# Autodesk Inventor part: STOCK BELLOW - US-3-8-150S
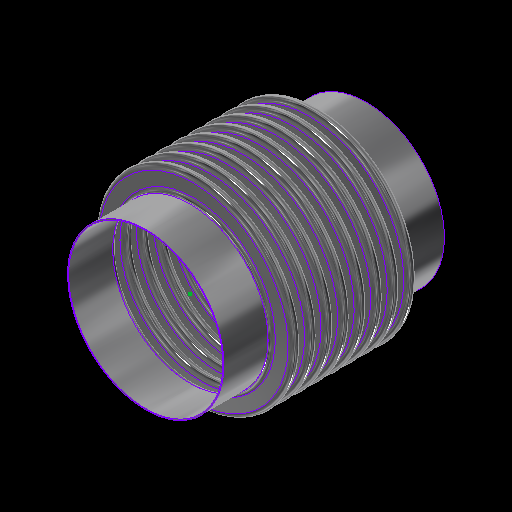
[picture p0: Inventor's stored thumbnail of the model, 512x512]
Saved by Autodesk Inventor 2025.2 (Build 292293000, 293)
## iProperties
Category: 24 GA (0.024 THICK)
RuleStatus: InUse
Created: 2024-01
Part Number: STOCK BELLOW - US-3-8-150S
Project: =STOCK BELLOWS: <Stock Number><SFILL>
Material: ASTM A240-304
Description: =STOCK BELLOWS: <Stock Number>, <SID_> I.D., <SOD_> O.D., <SPLY_> PLY, <Category>, <SNET_CONS> CONS.<PITCH_><STANGENT_> TANGENT<SFILL>
Document SubType Name: Sheet Metal
Designer: GS
Stock Number: U.S-3-8-150S
Surface Area: 1808.55 cm^2
Volume: 54.8112 cm^3
Sheet Metal Rule: Default
Appearance: STAINLESS STEEL
Mass: 441.629 g
Density: 8.05729 g/cm^3
THK: 0.036
ID: 3.500
OD: 4.250
CONS_: 2
PITCH: 0.500
TANGENT: 0.500
BELLOWS_UPSET: 0.000
d79: 1.000
d82: 1.000
d83: 26.000
d84: 24.000
d174: 8
d214: 8
STHK_: 0.024
SID_: 3.500
SOD_: 4.500
SPITCH_: 0.375
STANGENT__: 1.000
SBELLOWS_UPSET_: 0.000
SDIFF_TAN: 1.000
d252: 2
d275: 2
d287: 0.050
d289: 0.500
d290: 0.000
SOD_NECK: 3 9/16
PLY: 1
PSET: 4.178
PBAR: 1.035
COUNTER: 1.500
NET_TUBE: 3.071
CONS: 2
S_CONS: 0
NET_CONS: 2
ID_M: 88.90 mm
OD_M: 107.95 mm
THK_M: 0.91 mm
ID_U: 3.500 in
OD_U: 4.250 in
THK_U: 0.036 in
TANGENT2: 0.500
TAN_TO_TAN: 1.000 in
d80: 2.571
d81: 10
SID: 2.375
SCONS_: 8
SPITCH: 0.250
STANGENT_: 1.000
SBELLOWS_UPSET: 0.000
SNET_CONS: 8
SS_CONS: 0
SCONS: 8
d190: 8
d191: 1
d192: 1
d193: 8
d194: 0
SIZE: 3.00
PRESSURE: 150
d230: 8
STANGENT: 4.000
SPLY_: 1
d233: 8
d234: 0
d263: 2
d265: 1
d268: 2
d269: 0
d286: 2
d288: 1
d291: 2
d292: 0
SREROLL: 0.750
BLETP: 0.000 ul
PRES_Copy: 85
MATTABLE: 20 GA (0.036 THICK)
PART_NUMBER: U.S-3-8-150S
PITCH_: =, <SPITCH_> PITCH,
CFILL: .
SFILL: .
MESH: ,
COMP: 0.66
EXT: 0.33
LAT: 0.16
ANG: 573
ASR: 950
LSR: 2281
ANSR: 30
PRES: 150
COMPM: 6.6
EXTM: 3.3
LATM: 1.60
ASRM: 166.374
PRESM: 10.342
LSRM: 399.472
ANSRM: 5.254
TEMPMIN: 20
TEMPMAX: 800
TEMPMINM: -7
TEMPMAXM: 427
WEIGHTM: 0.442
WEIGHT: 0.974
Author: GS
Keywords: 20 GA (0.036 THICK)
Comments: =STOCK BELLOW - <STOCK NUMBER>
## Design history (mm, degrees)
sketch "Sketch2"
  geometry: L1 (0, -177.245)-(0, 562.856) reference; L2 (45.364, 0)-(44.45, 0); L3 (48.082, -2.718)-(50.343, -2.718); L4 (48.082, -3.632)-(50.343, -3.632); L5 (50.343, -9.982)-(48.082, -9.982); L6 (50.343, -9.068)-(48.082, -9.068); L7 (45.364, -12.7)-(44.45, -12.7); L8 (48.082, 0)-(48.082, -12.7); L9 (50.343, -6.35)-(53.975, -6.35); L10 (44.45, 0)-(44.45, -12.7); L11 (20.376, 102.841)-(20.376, 101.926); L12 (58.262, 457.127)-(58.262, 349.177); L13 (58.262, 444.427)-(58.262, 336.477); L14 (93.133, -58.817)-(93.133, -71.517); L15 (118.746, -66.401)-(118.746, -66.401); L16 (50.343, -9.068)-(50.343, -9.982); L17 (48.082, -9.068)-(48.082, -9.982); L18 (48.082, -9.525)-(50.343, -9.525); L19 (53.975, 0)-(53.975, -12.7); L20 (-50.343, -9.068)-(-50.343, -9.982); L21 (-50.343, -2.718)-(-48.082, -2.718); L22 (-50.343, -3.632)-(-48.082, -3.632); L23 (-48.082, -9.068)-(-50.343, -9.068); L24 (-50.343, -9.525)-(-48.082, -9.525); L25 (-48.082, -9.982)-(-50.343, -9.982); L26 (-48.082, -9.068)-(-48.082, -9.982); L27 (-44.45, 0.653)-(-44.45, -12.047); L28 (-48.082, -6.35)-(-44.45, -6.35); L29 (-50.343, 0.653)-(-50.343, -12.7); L30 (-53.061, 0)-(-53.975, 0); L31 (-53.975, 0)-(-53.975, -12.7); L32 (-53.061, -12.7)-(-53.975, -12.7); A1 r 2.718 centre (48.082, 0) between (45.364, 0) and (48.082, -2.718); A2 r 3.632 centre (48.082, 0) between (44.45, 0) and (48.082, -3.632); A3 r 3.632 centre (50.343, -6.35) between (50.343, -9.982) and (50.343, -2.718); A4 r 2.718 centre (50.343, -6.35) between (50.343, -9.068) and (50.343, -3.632); A5 r 2.718 centre (48.082, -12.7) between (48.082, -9.982) and (45.364, -12.7); A6 r 3.632 centre (48.082, -12.7) between (48.082, -9.068) and (44.45, -12.7); A7 r 3.175 centre (50.343, -6.35) between (50.343, -9.525) and (53.518, -6.35); A8 r 3.175 centre (48.082, -12.7) between (48.082, -9.525) and (44.907, -12.7); A9 r 2.718 centre (-50.343, -12.7) between (-50.343, -9.982) and (-53.061, -12.7); A10 r 2.718 centre (-48.082, -6.35) between (-48.082, -9.068) and (-48.082, -3.632); A11 r 3.175 centre (-48.082, -6.35) between (-48.082, -9.525) and (-44.907, -6.35); A12 r 3.632 centre (-48.082, -6.35) between (-48.082, -9.982) and (-48.082, -2.718); A13 r 3.175 centre (-50.343, -12.7) between (-50.343, -9.525) and (-53.518, -12.7); A14 r 3.632 centre (-50.343, -12.7) between (-50.343, -9.068) and (-53.975, -12.7); A15 r 2.718 centre (-50.343, 0) between (-53.061, 0) and (-50.343, -2.718); A16 r 3.632 centre (-50.343, 0) between (-53.975, 0) and (-50.343, -3.632); 10 further points
  constraints: 62 end point, 38 point on circle, 20 tangent, 16 centre point, 12 parallel, 9 midpoint, 7 vertical, 6 coincident, 6 concentric, 6 point on line, 4 equal radius, 4 perpendicular, 3 horizontal, 1 collinear, 1 horizontal alignment, 10 other
  dimensions: "THK" = 0.9144 distance of L11.start L11.end; "ID" = 88.9 distance of L11.end point (20.376, 13.026); "OD" = 107.95 distance of L12.start L12.end; "PITCH" = 12.7 distance of L12.start L13.start; "TANGENT" = 12.7 distance of L14.start L14.end; "BELLOWS_UPSET" = 0 distance of L15.start L15.end; "d43" = 88.9 diameter of L10 L1 (= ID); "d44" = 107.95 diameter of L9.end L1 (= OD); "d45" = 0.9144 distance between parallel lines of L5 L6 (computed from THK, PLY); "d46" = 3.6322 radius of A3 (computed from PITCH, THK, PLY); "UPSET_PITCH" = 12.7 distance of L2.end L7.end (derived); "SIDEWALL_ANGLE" = 360 deg dimension on L3 L9 (derived); "CON_GAP" = 5.4356 distance of point (48.082, -9.068) point (48.082, -3.632) (derived); "TAN1" = 4.98728 dimension on A8 (derived); "TAN2" = 4.98728 dimension on A7 (derived); "LEG1" = 2.2606 distance of L18.start L18.end (derived); "d278" = 0.9144 distance between parallel lines of L25 L23 (derived); "d279" = 3.6322 radius of A12 (derived); "d280" = 12.7 distance of L30.end L31.end (derived); "d281" = 360 deg dimension on L21 L28 (derived); "d282" = 5.4356 distance of point (-50.343, -9.068) point (-50.343, -3.632) (derived); "d283" = 4.98728 dimension on A13 (derived); "d284" = 4.98728 dimension on A11 (derived); "d285" = 2.2606 distance of L24.start L24.end (derived); "d293" = 88.9 diameter of L27 L1 (derived); "d294" = 107.95 diameter of L31 L1 (derived)
  node "Sketch Rectangular Pattern1" dims "d31" = 25.4, "ID" = 88.9
  node "Sketch Rectangular Pattern2" dims "d39" = 25.4, "PITCH" = 12.7
revolve "CONS" stored, may be unused: angle "d48" = 90 deg
node "BELLOW MIDPLANE"
pattern_linear "Rectangular Pattern2" dims "d52" = 12.7 (= UPSET_PITCH)
sketch "Sketch5"
  geometry: C1 r 45.364 at (0, 0) reference; C2 r 44.45 at (0, 0) reference
extrude "TANGENT" new body sketch "Sketch5" distance "d53" = 12.7 (= TANGENT); taper "d54" = 0 deg
revolve "SAMETAN" stored, may be unused: angle "d65" = 90 deg
revolve "DIFFTAN" stored, may be unused: angle "d70" = 90 deg
sketch "Sketch9"
  geometry: L1 (53.319, 0)-(-53.319, 0) reference; L2 (0, -17.78)-(0, 17.78) reference; L3 (38.085, 0)-(-38.085, 0); L4 (38.085, -11.906)-(38.085, 11.906); L5 (25.385, -11.906)-(25.385, 11.906); L6 (13.15, 11.906)-(13.15, -11.906); L7 (-25.385, -11.906)-(-25.385, 11.906); L8 (-38.085, -11.906)-(-38.085, 11.906); L9 (37.291, -11.906)-(37.291, 11.906); L10 (38.085, -11.906)-(37.291, -11.906); L11 (38.085, 11.906)-(37.291, 11.906); L12 (13.546, 11.906)-(12.753, 11.906); L13 (12.753, 11.906)-(12.753, -11.906); L14 (12.753, -11.906)-(13.546, -11.906); L15 (13.546, -11.906)-(13.546, 11.906); L16 (-13.546, 11.906)-(-13.546, -11.906); L17 (-13.15, 11.906)-(-13.15, -11.906); L18 (-13.546, -11.906)-(-12.753, -11.906); L19 (-12.753, -11.906)-(-12.753, 11.906); L20 (-12.753, 11.906)-(-13.546, 11.906); L21 (-38.085, -11.906)-(-37.291, -11.906); L22 (-37.291, -11.906)-(-37.291, 11.906); L23 (-37.291, 11.906)-(-38.085, 11.906); L24 (-38.085, 11.906)-(-38.085, -11.906); L25 (38.085, -0.397)-(-38.085, -0.397); L26 (-38.085, -0.397)-(-38.085, 0.397); L27 (-38.085, 0.397)-(38.085, 0.397); L28 (38.085, 0.397)-(38.085, -0.397); L29 (-38.085, 11.906)-(38.085, 11.906); L30 (38.085, 11.906)-(38.085, 12.7); L31 (38.085, 12.7)-(-38.085, 12.7); L32 (-38.085, 12.7)-(-38.085, 11.906); L33 (38.085, -11.906)-(-38.085, -11.906); L34 (-38.085, -11.906)-(-38.085, -12.7); L35 (-38.085, -12.7)-(38.085, -12.7); L36 (38.085, -12.7)-(38.085, -11.906); 30 further points
  constraints: 68 end point, 13 midpoint, 13 parallel, 8 horizontal, 7 perpendicular, 6 equal length, 3 point on line, 2 vertical, 14 other
  dimensions: "d115" = 23.8125 distance of L4.start L4.end (derived); "d116" = 12.7 distance between parallel lines of L4 L5 (derived); "d117" = 12.23516 distance between parallel lines of L5 L6 (derived); "d125" = 38.53427 distance between parallel lines of L7 L6 (derived); "d127" = 12.7 distance between parallel lines of L8 L7 (derived); "d128" = 24.93516 distance between parallel lines of L6 L4 (derived); "d130" = 76.16943 distance between parallel lines of L8 L4 (derived); "RULER_THK" = 0.79375 distance between parallel lines of L4 L9; "d135" = 0.79375 distance of L13.end L14.end (derived); "d138" = 26.29911 distance of L13.end L16.end (derived); "d143" = 0.79375 distance of L22.end L8.end (derived); "d144" = 0.79375 distance between parallel lines of L27 L25 (derived)
extrude "RULER" join sketch "Sketch9" distance "d149" = 0.79375 (derived); taper "d150" = 0 deg
extrude "BARS" join sketch "Sketch9" distance "d151" = 0.79375 (derived); taper "d152" = 0 deg
pattern_linear "Rectangular Pattern4" dims "d155" = 26.29911 (derived)
sketch "Sketch13"
  geometry: L1 (93.149, -52.467)-(93.149, -77.867); L2 (45.06, 0)-(44.45, 0); L3 (45.06, -9.525)-(44.45, -9.525); L4 (54.464, -7.449)-(47.136, -7.449); L5 (54.464, -6.839)-(47.136, -6.839); L6 (54.464, -4.763)-(57.15, -4.763); L7 (47.136, -2.076)-(54.464, -2.076); L8 (47.136, 0)-(47.136, -9.525); L9 (44.45, 0)-(44.45, -9.525); L10 (58.254, -382.131)-(58.254, -496.431); L11 (58.254, -391.656)-(58.254, -505.956); L12 (58.254, -410.706)-(58.254, -525.006); L13 (58.254, -420.231)-(58.254, -534.531); L14 (58.254, -429.756)-(58.254, -544.056); L15 (58.254, -439.281)-(58.254, -553.581); L16 (58.254, -448.806)-(58.254, -563.106); L17 (58.254, -401.181)-(58.254, -515.481); L18 (20.376, 102.536)-(20.376, 101.926); L19 (47.136, -2.686)-(54.464, -2.686); L20 (0, -696.234)-(0, 235.664) reference; L21 (-23.752, 0)-(142.514, 0) reference; A1 r 2.076 centre (47.136, 0) between (45.06, 0) and (47.136, -2.076); A2 r 2.076 centre (47.136, -9.525) between (47.136, -7.449) and (45.06, -9.525); A3 r 2.686 centre (47.136, -9.525) between (47.136, -6.839) and (44.45, -9.525); A4 r 2.076 centre (54.464, -4.763) between (54.464, -6.839) and (54.464, -2.686); A5 r 2.686 centre (54.464, -4.763) between (54.464, -7.449) and (54.464, -2.076); A6 r 2.686 centre (47.136, 0) between (44.45, 0) and (47.136, -2.686); 6 further points; 1 other entity
  constraints: 38 end point, 15 point on circle, 9 tangent, 6 centre point, 6 parallel, 5 vertical alignment, 4 point on line, 4 vertical, 3 coincident, 3 concentric, 2 collinear, 2 equal radius, 1 horizontal, 1 perpendicular, 23 other
  dimensions: "SBELLOWS_UPSET_" = 0 distance of point (118.762, -66.401) point (118.762, -66.401); "STOTAL_THK_BELLOW__" = 0.6096 distance between parallel lines of L4 L5 (derived); "d224" = 2.68605 radius of A5 (derived); "d225" = 9.525 distance of L2.end L3.end (derived); "SSIDEWALL_ANGLE_" = 0 deg angle of L7 L6 (derived); "SSCON_GAP_" = 4.1529 distance of point (47.136, -6.839) point (47.136, -2.686) (derived); "d235" = 88.9 diameter of L9 L20 (derived); "d236" = 114.3 diameter of L6.end L20 (derived)
  node "Sketch Rectangular Pattern4" dims "d228" = 25.4
  node "Sketch Rectangular Pattern5" dims "d229" = 25.4
revolve "SBELLOW" stored, may be unused: angle "d197" = 90 deg
pattern_linear "Rectangular Pattern5" dims "d204" = 9.525 (derived)
revolve "STANGENT" stored, may be unused: angle "d240" = 90 deg
revolve "SSAMETAN" stored, may be unused: angle "d241" = 90 deg
revolve "SDIFFTAN" stored, may be unused: angle "d246" = 90 deg
revolve "INVCON" stored, may be unused: angle "d295" = 90 deg
pattern_linear "Rectangular Pattern6" dims "d298" = 12.7 (derived)
revolve "INVTANGENT" stored, may be unused: angle "d302" = 90 deg
revolve "INVSAMETAN" stored, may be unused: angle "d307" = 90 deg
revolve "INVDIFFTAN" stored, may be unused: angle "d312" = 90 deg
sketch "ID BELLOW MOUNT CALC"
  geometry: L1 (44.45, 0)-(38.1, 0); L2 (38.1, 0)-(38.1, 12.7); L3 (38.1, 12.7)-(44.45, 12.7); L4 (44.45, 12.7)-(44.45, 0); L5 (36.513, 12.7)-(35.598, 12.7); L6 (35.598, 12.7)-(35.598, 0); L7 (35.598, 0)-(36.513, 0); L8 (36.513, 0)-(36.513, 12.7); L9 (0, -2.54)-(0, 15.24) reference; L10 (-8.89, 0)-(53.34, 0) reference; 1 further point
  constraints: 16 end point, 5 parallel, 2 collinear, 2 horizontal, 2 perpendicular
  dimensions: "d314" = 12.7 distance of L5.end L6.end (derived); "d315" = 0.9144 distance of L5.start L5.end (derived); "IG" = 1.5875 distance between parallel lines of L2 L8; "PIPE_OD" = 88.9 diameter of L4 L9; "PIPE_WALL" = 6.35 distance of L2.end L3.end; "ID_MT_BELLOW" = 71.1962 diameter of L6 L9 (derived)
revolve "CFILL" stored, may be unused: angle "d320" = 90 deg
pattern_linear "Rectangular Pattern7" dims "d323" = 12.7 (derived)
revolve "SFILL" stored, may be unused: angle "d324" = 90 deg
pattern_linear "Rectangular Pattern8" dims "d327" = 9.525 (derived)
node "STOCK BELLOW MIDPLANE"
node "BELLOW"
sketch "Sketch6"
  geometry: L1 (-12.7, 45.364)-(0, 45.364); L2 (0, 45.364)-(0, 44.45); L3 (0, 44.45)-(-12.7, 44.45); L4 (-12.7, 44.45)-(-12.7, 45.364); L5 (10.16, 0)-(-60.96, 0) reference; L6 (-38.1, -89.422)-(-38.1, 153.44) reference; 1 further point
  constraints: 8 end point, 2 parallel, 1 horizontal, 1 perpendicular
  dimensions: "d61" = 12.7 distance of L2.end L3.end (derived); "d62" = 0.9144 distance of L1.end L2.end (derived); "d63" = 88.9 diameter of L3 L5 (derived); "d64" = 25.4 distance between parallel lines of L4 L6 (derived)
sketch "Sketch12"
  geometry: 1 further point
sketch "Sketch14"
  geometry: L1 (-25.4, 45.06)-(0, 45.06); L2 (0, 45.06)-(0, 44.45); L3 (0, 44.45)-(-25.4, 44.45); L4 (-25.4, 44.45)-(-25.4, 45.06); L5 (5.08, 0)-(-30.48, 0) reference; L6 (0, -9.012)-(0, 54.072) reference; 1 further point
  constraints: 8 end point, 2 parallel, 1 collinear, 1 horizontal, 1 perpendicular
  dimensions: "d237" = 0.6096 distance of L3.end L1.start (derived); "d238" = 88.9 diameter of L3 L5 (derived); "d239" = 25.4 distance of L1.start L1.end (derived); "SOD_NECK" = 90.1192 diameter of L1 L5 (derived)
sketch "Sketch15"
  geometry: L1 (-9.012, 0)-(54.072, 0) reference; L2 (44.45, -76.2)-(45.06, -76.2); L3 (45.06, -76.2)-(45.06, -101.6); L4 (45.06, -101.6)-(44.45, -101.6); L5 (44.45, -101.6)-(44.45, -76.2); L6 (0, -124.46)-(0, 35.56) reference; 1 further point
  constraints: 8 end point, 2 parallel, 1 horizontal, 1 perpendicular
  dimensions: "d205" = 25.4 distance of L4.end L2.start (derived); "d206" = 0.6096 distance of L3.end L4.end (derived); "d207" = 88.9 diameter of L5 L6 (derived); "d208" = 76.2 distance between parallel lines of L1 L2 (derived)
node "TANGENT_"
node "SAME_TAN"
sketch "Sketch8"
  geometry: L1 (45.364, -25.4)-(44.45, -25.4); L2 (44.45, -25.4)-(44.45, -38.1); L3 (44.45, -38.1)-(45.364, -38.1); L4 (45.364, -38.1)-(45.364, -25.4); L5 (0, -48.26)-(0, 22.86) reference; L6 (-89.422, 0)-(153.44, 0) reference; 1 further point
  constraints: 8 end point, 2 parallel, 1 horizontal, 1 perpendicular
  dimensions: "d66" = 88.9 diameter of L2 L5 (derived); "TOTAL_THK_BELLOW" = 0.9144 distance of L2.end L3.end (derived); "d68" = 25.4 distance between parallel lines of L1 L6 (derived); "d69" = 12.7 distance of L1.end L2.end (derived)
node "DIFF_TAN"
node "Sketch Rectangular Pattern3" dims "d138" = 26.29911 (derived), "d141" = 25.4
node "SBELLOW_"
node "STANGENT_"
node "SSAME_TAN"
sketch "Sketch16"
  geometry: L1 (45.06, -76.2)-(44.45, -76.2); L2 (44.45, -76.2)-(44.45, -101.6); L3 (44.45, -101.6)-(45.06, -101.6); L4 (45.06, -101.6)-(45.06, -76.2); L5 (0, -124.46)-(0, 35.56) reference; L6 (-9.012, 0)-(54.072, 0) reference; 1 further point
  constraints: 8 end point, 2 parallel, 1 horizontal, 1 perpendicular
  dimensions: "SDIFF_TAN" = 25.4 distance of L3.end L1.start; "d243" = 0.6096 distance of L2.end L3.end (derived); "d244" = 76.2 distance between parallel lines of L1 L6 (derived); "d245" = 88.9 diameter of L2 L5 (derived)
node "SDIFF_TAN"
body "Solid15"
sketch "Sketch17"
  geometry: L1 (53.975, 12.7)-(53.061, 12.7); L2 (53.061, 12.7)-(53.061, 0); L3 (53.061, 0)-(53.975, 0); L4 (53.975, 0)-(53.975, 12.7); L5 (0, -2.54)-(0, 15.24) reference; L6 (-10.795, 0)-(64.77, 0) reference; 2 further points
  constraints: 8 end point, 2 parallel, 1 horizontal, 1 midpoint, 1 perpendicular, 1 point on line
  dimensions: "INVTANGENT" = 12.7 distance of L3.end L1.start (derived); "d300" = 0.9144 distance of L1.start L1.end (derived); "d301" = 107.95 diameter of L4 L5 (derived)
body "Solid16"
sketch "Sketch18"
  geometry: L1 (53.975, -25.4)-(53.061, -25.4); L2 (53.061, -25.4)-(53.061, -38.1); L3 (53.061, -38.1)-(53.975, -38.1); L4 (53.975, -38.1)-(53.975, -25.4); L5 (-10.795, 0)-(64.77, 0) reference; L6 (0, -48.26)-(0, 22.86) reference; 1 further point
  constraints: 8 end point, 2 parallel, 1 horizontal, 1 perpendicular
  dimensions: "d303" = 25.4 distance between parallel lines of L1 L5 (derived); "d304" = 12.7 distance of L3.end L1.start (derived); "d305" = 0.9144 distance of L2.end L3.end (derived); "d306" = 107.95 diameter of L4 L6 (derived)
body "Solid17"
sketch "Sketch19"
  geometry: L1 (53.975, -25.4)-(53.061, -25.4); L2 (53.061, -25.4)-(53.061, -38.1); L3 (53.061, -38.1)-(53.975, -38.1); L4 (53.975, -38.1)-(53.975, -25.4); L5 (0, -48.26)-(0, 22.86) reference; L6 (-10.795, 0)-(64.77, 0) reference; 1 further point
  constraints: 8 end point, 2 parallel, 1 horizontal, 1 perpendicular
  dimensions: "d308" = 12.7 distance of L1.end L2.end (derived); "d309" = 107.95 diameter of L4 L5 (derived); "d310" = 0.9144 distance of L2.end L3.end (derived); "d311" = 25.4 distance between parallel lines of L1 L6 (derived)
body "Solid18"
body "Solid19"
body "Solid20"
other parameters: "BMPL" = -38.1, "PSET" = 106.1212 (computed from OD, THK, PLY) [user parameter], "PBAR" = 26.29911 (= 0.570796 x PITCH + OD - ID) [user parameter; used in 1 equation term], "COUNTER" = 15 [user parameter], "NET_TUBE" = 77.99823 (computed from CONS_, PBAR, TANGENT) [user parameter], "S_CONS" = 0 [user parameter; used in 1 equation term], "ID_M" = 88.9 (= ID) [user parameter], "OD_M" = 107.95 (= OD) [user parameter], "THK_M" = 0.9144 (= THK) [user parameter], "ID_U" = 88.9 (= ID) [user parameter], "OD_U" = 107.95 (= OD) [user parameter], "THK_U" = 0.9144 (= THK) [user parameter], "D_UNITS" = 0 [user parameter], "TANGENT2" = 12.7 [user parameter], "TAN_TO_TAN" = 25.4 [user parameter], "OD_NECK" = 90.7288 [user parameter], "d79" = 25.4, "d80" = 65.29823 [user parameter], "d82" = 25.4, "d83" = 660.4, "d84" = 609.6, "sa_0" = 4, "FRAME_THK" = 0.79375 [user parameter], "CON_FLAT" = 12.23516 [user parameter], "SID" = 60.325 [user parameter], "SPITCH" = 6.35 [user parameter], "STANGENT_" = 25.4 [user parameter], "SBELLOWS_UPSET" = 0 [user parameter], "SS_CONS" = 0 [user parameter], "STAN_TO_TAN_" = 76.2 [user parameter], "d100" = 0.6096 [user parameter], "d191" = 25.4 [user parameter], "d194" = 0 [user parameter], "STANGENT" = 101.6 [user parameter], "d234" = 0 [user parameter], "SUPSET_PITCH_" = 9.525 [user parameter], "d269" = 0 [user parameter], "d287" = 1.27, "d289" = 12.7, "d290" = 0, "d292" = 0 [user parameter], "Thickness" = 3.048 (derived), "KFactor" = 4.4, "BendRadius" = 3.048 (derived), "BendReliefWidth" = 3.048 (derived), "BendReliefDepth" = 1.524 (derived), "CornerReliefSize" = 12.192 (derived), "SeamGap" = 0.00508, "MinimumRemnant" = 6.096 (derived), "TransitionRadius" = 3.048 (derived), "JacobiRadiusSize" = 3.048 (derived), "GapSize" = 3.048 (derived), "SREROLL" = 19.05 [user parameter], "CUR_STK_PITCH" = 9.525 [user parameter], "d328" = -38.1 (derived), "LSR" = 22810 [user parameter], "BLETP" = 0 [user parameter], "ASRM" = 1663.735 [user parameter], "PRESM" = 103.41975 [user parameter], "LSRM" = 3994.7153 [user parameter], "ANSRM" = 52.539 [user parameter], "TEMPMIN" = 2664.83333 [user parameter], "TEMPMAX" = 6998.16667 [user parameter], "TEMPMINM" = 2664.83333 [user parameter], "TEMPMAXM" = 6998.16667 [user parameter], "WEIGHT" = 4.41629 [user parameter], "WEIGHTM" = 0.00442 [user parameter]
